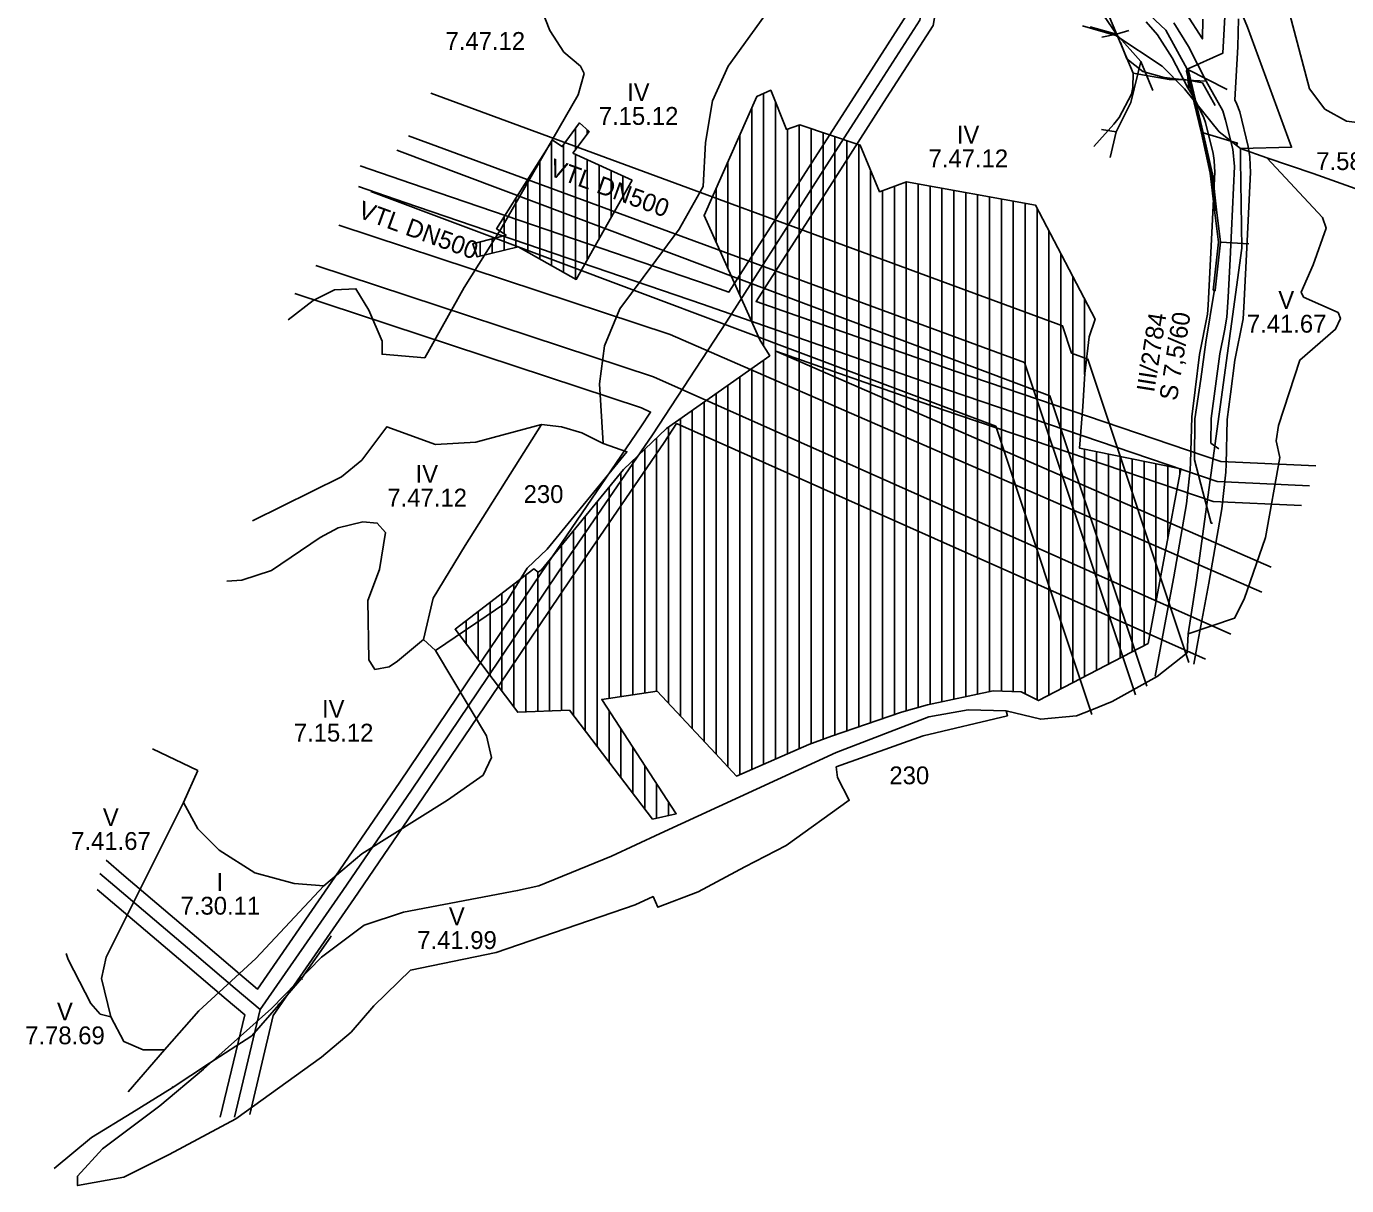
# Model space of a CAD drawing. Extents: x -694504 to -690518, y -983661 to -978958.
# Drawn here: x -694504 to -693394, y -982493 to -981518 of the extents above; entities that cross this region are included whole.
import ezdxf

# ---------------------------------------------------------------- set-up
doc = ezdxf.new("R2010")
doc.units = 0
for name, color, linetype in [('bezpečnostní pásmo', 7, 'Continuous'), ('BPEJ', 7, 'Continuous'), ('kabelové a venkovní rozvody telefonu', 7, 'Continuous'), ('ochranné pásmo silnic', 7, 'Continuous'), ('ochranné pásmo vedení', 7, 'Continuous'), ('odvodněné pozemky', 7, 'Continuous'), ('třídy přednosti v ochraně ZP', 7, 'Continuous'), ('vedení NN', 7, 'Continuous'), ('vedení VN 35kV', 7, 'Continuous'), ('vedení VVN 110kV', 7, 'Continuous'), ('vedení VVN 220kV', 7, 'Continuous'), ('vedení VVN 400kV', 7, 'Continuous'), ('vodovodní řad', 7, 'Continuous'), ('VTL plynovod', 7, 'Continuous')]:
    doc.layers.add(name, color=color, linetype=linetype)

msp = doc.modelspace()

# ---------------------------------------------------------------- linework, layer by layer
at = {"layer": 'bezpečnostní pásmo'}
for points in [[(-693526.8, -982053), (-693611.7, -981798.1), (-693625.5, -981792.9), (-693633.2, -981769.9), (-694164.4, -981574.4)], [(-694214.8, -981657), (-693689.3, -981854.4), (-693608.5, -982096.8)]]:
    msp.add_lwpolyline(points, dxfattribs=at)
at = {"layer": 'BPEJ'}
for p, q in [((-694263.4, -981748.8), (-694284.2, -981764.8)), ((-694323.4, -981983.8), (-694335.8, -981984.6)), ((-694360.4, -982143.8), (-694398.3, -982125.5)), ((-694372.4, -982170.8), (-694360.4, -982143.8)), ((-694469.4, -982302.8), (-694471.1, -982297.6)), ((-694450.4, -982339.8), (-694469.4, -982302.8)), ((-694442.4, -982348.8), (-694450.4, -982339.8)), ((-694433.4, -982350.8), (-694442.4, -982348.8)), ((-694419, -982413.9), (-694388.4, -982378.8))]:
    msp.add_line(p, q, dxfattribs=at)
for points in [[(-694038.4, -981384.8), (-694071.4, -981426.8), (-694078.4, -981449.8), (-694078.4, -981485.8), (-694064.4, -981521.8), (-694052.4, -981539.8), (-694038.4, -981551.8), (-694035.4, -981557.8), (-694040.4, -981575.8), (-694105.4, -981688.8), (-694136.4, -981737.8), (-694169.4, -981796.8), (-694205.4, -981793.8), (-694205.4, -981782.8), (-694216.4, -981756.8), (-694227.4, -981738.8), (-694245.4, -981739.8), (-694263.4, -981748.8)], [(-693904.4, -981450.8), (-693893.4, -981452.8), (-693883.4, -981459.8), (-693874.4, -981467.8), (-693870.4, -981480.8), (-693873.4, -981494.8), (-693914.4, -981551.8), (-693927.4, -981580.8), (-693933.4, -981615.8), (-693935.4, -981652.8), (-693955.4, -981688.8), (-694005.4, -981755.8), (-694018.4, -981786.8), (-694022.4, -981818.8), (-694019.4, -981868.8)], [(-693237.4, -981494.8), (-693223.4, -981526.8), (-693218.4, -981584.8), (-693210.4, -981605.8), (-693195.4, -981621.8), (-693120.4, -981666.8), (-693101.4, -981671.8), (-693080.4, -981680.8), (-693041.4, -981711.8), (-693078.4, -981753.8), (-693108.4, -981714.8), (-693141.4, -981687.8), (-693185.4, -981672.8), (-693254.4, -981657.8), (-693276.4, -981647.8), (-693345.4, -981606.8), (-693363.4, -981601.8), (-693394.4, -981597.8), (-693412.4, -981587.8), (-693425.4, -981570.8), (-693452.4, -981468.8)], [(-693492.4, -981482.8), (-693477.4, -981518.8), (-693440.4, -981619.8), (-693483.4, -981620.8), (-693501.4, -981606.8), (-693530.4, -981570.8), (-693549.4, -981551.8), (-693588.4, -981525.8), (-693616.4, -981517.8)], [(-693461.4, -981628.8), (-693422.4, -981641.8), (-693352.4, -981666.8)], [(-694071.4, -981852.8), (-694126.4, -981867.8), (-694160.4, -981869.8), (-694201.4, -981854.8), (-694222.4, -981882.8), (-694239.4, -981896.8), (-694314.4, -981933.8)], [(-694170.4, -982033.8), (-694192.4, -982051.8), (-694199.4, -982056.8), (-694211.4, -982058.8), (-694216.4, -982050.8), (-694217.4, -982000.8), (-694207.4, -981974.8), (-694202.4, -981943.8), (-694209.4, -981935.8), (-694221.4, -981934.8), (-694242.4, -981939.8), (-694257.4, -981947.8), (-694298.4, -981975.8), (-694323.4, -981983.8)], [(-693680.4, -982093.8), (-693651.4, -982100.8), (-693621.4, -982097.8), (-693608.4, -982092.8), (-693591.4, -982085.8), (-693553.4, -982064.8), (-693528.4, -982044.8), (-693527.4, -982028.8)], [(-694254.4, -982240.8), (-694222.4, -982213.8), (-694150.4, -982168.8), (-694120.4, -982147.8), (-694113.4, -982132.8), (-694117.4, -982114.8), (-694160.4, -982042.8)]]:
    msp.add_lwpolyline(points, dxfattribs=at)
for points in [[(-693461.4, -981628.8), (-693414.4, -981678.8), (-693411.4, -981687.8), (-693422.4, -981718.8), (-693432.4, -981741.8), (-693430.4, -981745.8), (-693401.4, -981758.8), (-693399.4, -981763.8), (-693403.4, -981772.8), (-693433.4, -981798.8), (-693451.4, -981853.8), (-693453.4, -981866.8), (-693450.4, -981880.8), (-693462.4, -981947.8), (-693480.4, -981999.8), (-693488.4, -982015.8), (-693527.4, -982028.8), (-693520.4, -981983.8), (-693482.4, -981704.8), (-693483.4, -981630.8), (-693483.4, -981620.8), (-693461.4, -981628.8)], [(-694019.4, -981868.8), (-693999.4, -981875.8), (-694066.4, -981957.8), (-694083.4, -981973.8), (-694101.4, -982002.8), (-694160.4, -982042.8), (-694170.4, -982033.8), (-694162.4, -981998.8), (-694135.4, -981954.8), (-694071.4, -981852.8), (-694054.4, -981854.8), (-694037.4, -981859.8), (-694019.4, -981868.8)], [(-693680.4, -982093.8), (-693679.4, -982097.8), (-693750.4, -982114.8), (-693823.4, -982140.8), (-693822.4, -982149.8), (-693812.4, -982168.8), (-693865.4, -982206.8), (-693900.4, -982224.8), (-693939.4, -982245.8), (-693973.4, -982258.8), (-693977.4, -982249.8), (-693992.4, -982256.8), (-694109.4, -982296.8), (-694181.4, -982311.8), (-694212.4, -982341.8), (-694231.4, -982363.8), (-694256.4, -982384.8), (-694328.4, -982436.8), (-694384.4, -982466.8), (-694422.4, -982485.8), (-694461.4, -982492.8), (-694461.4, -982484.8), (-694440.4, -982461.8), (-694392.4, -982425.8), (-694355.4, -982394.8), (-694298.4, -982343.8), (-694256.4, -982300.8), (-694220.4, -982273.8), (-694187.4, -982262.8), (-694091.4, -982244.8), (-694073.4, -982240.8), (-694012.4, -982215.8), (-693971.4, -982196.8), (-693823.4, -982128.8), (-693745.4, -982098.8), (-693712.4, -982092.8), (-693680.4, -982093.8)], [(-694254.4, -982240.8), (-694311.4, -982301.8), (-694359.4, -982345.8), (-694388.4, -982378.8), (-694406.4, -982378.8), (-694422.4, -982371.8), (-694433.4, -982350.8), (-694441.4, -982318.8), (-694437.4, -982300.8), (-694372.4, -982170.8), (-694360.4, -982192.8), (-694342.4, -982210.8), (-694312.4, -982229.8), (-694279.4, -982238.8), (-694254.4, -982240.8)]]:
    msp.add_lwpolyline(points, close=True, dxfattribs=at)
at = {"layer": 'kabelové a venkovní rozvody telefonu'}
for points in [[(-693501.7, -981873.5), (-693508.5, -981868.6), (-693508, -981847.9), (-693500.7, -981793.5), (-693496.8, -981774.2), (-693494.8, -981762.6), (-693493.8, -981745.9), (-693492, -981714), (-693491, -981689.9), (-693488.4, -981636.1), (-693489.9, -981621.4), (-693496, -981597.1), (-693498.4, -981589.2), (-693512.3, -981564.3), (-693527.1, -981535.2), (-693539.4, -981515.1)], [(-693512.3, -981564.3), (-693528.4, -981563.5), (-693547.7, -981561.1), (-693565.6, -981556.1), (-693579.1, -981545.6), (-693584.3, -981531.8)]]:
    msp.add_lwpolyline(points, dxfattribs=at)
at = {"layer": 'ochranné pásmo silnic'}
for points in [[(-693562.8, -981514.3), (-693553.1, -981525.4), (-693541, -981544.6), (-693527.6, -981569.9), (-693520.8, -981581.7), (-693514.3, -981595.2), (-693512.9, -981599), (-693506.4, -981625), (-693505.6, -981630.9), (-693505.2, -981636.4), (-693505.1, -981640.6), (-693507.7, -981697.3), (-693510.6, -981752.6), (-693511.1, -981760.2), (-693517.8, -981794), (-693521.6, -981823.8), (-693524.4, -981846.6), (-693525.5, -981885.2), (-693525.7, -981890.9), (-693528.8, -981919.7), (-693539.5, -981981), (-693548.8, -982030.1), (-693555.3, -982064.6)], [(-693515, -981512.2), (-693515.5, -981528.8), (-693529, -981507.4)], [(-693522.7, -982054.3), (-693519.3, -982035.6), (-693510, -981986.3), (-693499.1, -981923.9), (-693495.8, -981893.1), (-693495.5, -981886.2), (-693494.5, -981848.8), (-693491.9, -981827.5), (-693488.2, -981798.8), (-693481.3, -981764), (-693480.7, -981754.3), (-693477.7, -981698.8), (-693475.1, -981640.9), (-693475.3, -981635.1), (-693475.7, -981627.9), (-693476.9, -981619.3), (-693484.1, -981590.2), (-693486.6, -981583.5), (-693488.3, -981579.9), (-693485.7, -981535.3), (-693485, -981512)]]:
    msp.add_lwpolyline(points, dxfattribs=at)
at = {"layer": 'ochranné pásmo vedení'}
for points in [[(-693651.4, -980679.7), (-693656.9, -980718.3), (-693667.6, -980824.3), (-693683.9, -980933.2), (-693690.1, -980989.4), (-693696.4, -981035.2), (-693702.4, -981085.5), (-693708.3, -981136.8), (-693719.8, -981230.7), (-693726.1, -981276.8), (-693732, -981321.5), (-693748.8, -981419.3), (-693764.3, -981508.7), (-693803.4, -981569.5), (-693844.2, -981633.2), (-693885.7, -981697.9), (-693913.6, -981741.6), (-693930.3, -981735.7), (-694180.6, -981650.3), (-694223.8, -981635.4)], [(-693420.2, -981887.7), (-693499.9, -981883.9), (-693723.4, -981808), (-693890.8, -981749.5), (-693865.9, -981710.6), (-693824.4, -981645.9), (-693783.6, -981582.2), (-693742, -981517.4), (-693725.6, -981423.3), (-693708.8, -981325), (-693702.8, -981280), (-693696.5, -981233.7), (-693685, -981139.6), (-693679, -981088.3), (-693674.5, -981050.1), (-693632.1, -981056.5), (-693561, -981067.7), (-693486.4, -981082.6), (-693375.3, -981103.5), (-693388.6, -981133.8), (-693412.6, -981189), (-693432.6, -981241.5), (-693452.6, -981307.6)], [(-694278.7, -981742.9), (-693987.2, -981839), (-693979.5, -981842.5), (-693987.7, -981855), (-694066.6, -981970.3), (-694126.4, -982059), (-694190.4, -982153.7), (-694248.1, -982238.1), (-694310.1, -982327.6), (-694321.4, -982318.1), (-694355.7, -982288.8), (-694422.4, -982232.1), (-694437.4, -982219.3)], [(-693457.6, -981972.8), (-693712.1, -981862), (-693874.3, -981791.3), (-693734.4, -981840.2), (-693506.3, -981917.6), (-693432.1, -981921.1)], [(-694316.7, -982432.9), (-694296.9, -982349.7), (-694228.7, -982251.4), (-694171, -982166.9), (-694106.9, -982072.1), (-694047.2, -981983.5), (-693968.2, -981868.1), (-693957.7, -981852.1), (-693740.7, -981948.8), (-693512.9, -982050.3)], [(-694444.9, -982243.8), (-694437.6, -982249.9), (-694371, -982306.7), (-694336.6, -982336), (-694320.9, -982349.2), (-694341.4, -982435.2)]]:
    msp.add_lwpolyline(points, dxfattribs=at)
at = {"layer": 'odvodněné pozemky'}
for p, q in [((-693884.5, -981787.1), (-693884.5, -981574.7)), ((-693874.5, -982134.3), (-693874.5, -981582)), ((-693894.5, -981766.8), (-693894.5, -981586.9)), ((-694042.8, -981622.1), (-694042.8, -981604.1)), ((-693854.5, -982125.6), (-693854.5, -981601.1)), ((-693844.5, -982121.4), (-693844.5, -981604.2)), ((-694062.8, -981719.4), (-694062.8, -981615.1)), ((-694032.8, -981608.8), (-694032.8, -981605.2)), ((-693904.5, -981744.5), (-693904.5, -981609.4)), ((-693864.5, -982129.9), (-693864.5, -981604.6)), ((-693834.5, -982117.6), (-693834.5, -981607.6)), ((-693824.5, -982113.9), (-693824.5, -981611)), ((-693814.5, -982110.5), (-693814.5, -981614.4)), ((-694052.8, -981725), (-694052.8, -981617.9)), ((-694042.8, -981730.5), (-694042.8, -981625.7)), ((-693804.5, -982107.1), (-693804.5, -981617.8)), ((-694072.8, -981713.8), (-694072.8, -981630.9)), ((-694032.8, -981714.5), (-694032.8, -981630.2)), ((-694022.8, -981696.8), (-694022.8, -981634.8)), ((-693914.5, -981722.1), (-693914.5, -981631.8)), ((-694082.8, -981708.3), (-694082.8, -981646.7)), ((-694012.8, -981679.1), (-694012.8, -981639.3)), ((-694002.8, -981661.4), (-694002.8, -981643.9)), ((-693794.5, -982103.7), (-693794.5, -981639.1)), ((-693924.5, -981699.7), (-693924.5, -981654.3)), ((-693784.5, -982100.3), (-693784.5, -981656.3)), ((-693774.5, -982097), (-693774.5, -981652.7)), ((-693764.5, -982093.8), (-693764.5, -981649.1)), ((-693754.5, -982090.8), (-693754.5, -981650.8)), ((-693744.5, -982088.1), (-693744.5, -981652.6)), ((-693734.5, -982086), (-693734.5, -981654.4)), ((-693724.5, -982083.8), (-693724.5, -981656.2)), ((-693714.5, -982081.7), (-693714.5, -981658)), ((-693704.5, -982079.6), (-693704.5, -981659.8)), ((-694092.8, -981704.1), (-694092.8, -981662.5)), ((-693694.5, -982077.4), (-693694.5, -981661.6)), ((-693684.5, -982077.1), (-693684.5, -981663.4)), ((-693674.5, -982077.4), (-693674.5, -981665.2)), ((-693664.5, -982079.4), (-693664.5, -981667)), ((-694102.8, -981692.5), (-694102.8, -981678.2)), ((-693934.5, -981677.3), (-693934.5, -981676.8)), ((-693654.5, -982084.4), (-693654.5, -981671.1)), ((-693644.5, -982080.3), (-693644.5, -981690.2)), ((-694122.8, -981711.2), (-694122.8, -981699.4)), ((-694112.8, -981708.9), (-694112.8, -981696.8)), ((-694102.8, -981706.5), (-694102.8, -981694.2)), ((-693634.5, -982075.1), (-693634.5, -981709.4)), ((-693624.5, -982069.9), (-693624.5, -981728.5)), ((-693614.5, -981810.8), (-693614.5, -981747.6)), ((-693884.5, -982138.6), (-693884.5, -981798.8)), ((-693904.5, -982147.3), (-693904.5, -981812.9)), ((-693894.5, -982142.9), (-693894.5, -981805.8)), ((-693914.5, -982140.8), (-693914.5, -981819.9)), ((-693934.5, -982119.5), (-693934.5, -981834)), ((-693924.5, -982130.2), (-693924.5, -981827)), ((-693954.5, -982098.1), (-693954.5, -981848.2)), ((-693944.5, -982108.8), (-693944.5, -981841.1)), ((-693964.5, -982087.3), (-693964.5, -981855.2)), ((-693974.5, -982077.1), (-693974.5, -981864.3)), ((-693984.5, -982078.6), (-693984.5, -981873.8)), ((-693614.5, -982064.7), (-693614.5, -981873.6)), ((-693604.5, -982059.5), (-693604.5, -981875.7)), ((-693594.5, -982054.3), (-693594.5, -981877.7)), ((-693584.5, -982049.2), (-693584.5, -981879.8)), ((-693574.5, -982044), (-693574.5, -981881.8)), ((-693994.5, -982080.1), (-693994.5, -981883.3)), ((-693564.5, -982038.8), (-693564.5, -981883.8)), ((-693554.5, -982001.2), (-693554.5, -981885.9)), ((-693544.5, -981948.1), (-693544.5, -981887.9)), ((-693534.5, -981895.1), (-693534.5, -981890)), ((-694004.5, -982081.6), (-694004.5, -981893.4)), ((-694014.5, -982083.1), (-694014.5, -981905.6)), ((-694024.5, -982123.7), (-694024.5, -981917.9)), ((-694034.5, -982110.6), (-694034.5, -981930.1)), ((-694044.5, -982097.4), (-694044.5, -981942.3)), ((-694054.5, -982093.4), (-694054.5, -981954.6)), ((-694064.5, -982093.8), (-694064.5, -981966.8)), ((-694084.5, -982094.7), (-694084.5, -981979.5)), ((-694074.5, -982094.2), (-694074.5, -981976.7)), ((-694094.5, -982090.7), (-694094.5, -981987.2)), ((-694114.5, -982064.1), (-694114.5, -982002.5)), ((-694104.5, -982077.4), (-694104.5, -981994.9)), ((-694124.5, -982050.8), (-694124.5, -982010.2)), ((-694134.5, -982037.6), (-694134.5, -982017.9)), ((-694014.5, -982136.8), (-694014.5, -982093.4)), ((-694004.5, -982149.9), (-694004.5, -982108.8)), ((-693994.5, -982163), (-693994.5, -982124.1)), ((-693984.5, -982176.2), (-693984.5, -982139.5)), ((-693974.5, -982184), (-693974.5, -982154.9)), ((-693964.5, -982181.7), (-693964.5, -982170.3))]:
    msp.add_line(p, q, dxfattribs=at)
for points in [[(-693561.2, -982037.1), (-693533.5, -981890.2), (-693618.9, -981872.7), (-693616, -981837.9), (-693614.4, -981810.1), (-693610.6, -981779.1), (-693605.7, -981764.5), (-693655.8, -981668.6), (-693764.2, -981649), (-693786.9, -981657.2), (-693803.2, -981618.2), (-693854, -981601), (-693865.3, -981604.9), (-693878.5, -981571.9), (-693890.2, -981577.3), (-693934.6, -981677.1), (-693887.5, -981782.4), (-693879.3, -981795.1), (-693966.1, -981856.4), (-694002.4, -981890.9), (-694071.3, -981975.2), (-694074, -981977), (-694077.7, -981974.3), (-694143.9, -982025.1), (-694091.3, -982094.9), (-694047.8, -982093.1), (-693977.9, -982184.7), (-693958, -982180.2), (-694020.6, -982084), (-693974.1, -982077), (-693925, -982129.6), (-693907.2, -982148.5), (-693846.5, -982122.1), (-693827.4, -982114.9)], [(-693994.9, -981647.5), (-694042, -981730.9), (-694091, -981703.7), (-694125.4, -981711.9), (-694129.1, -981701), (-694101, -981693.7), (-694109.1, -981688.3), (-694062, -981613.9), (-694053.8, -981619.3), (-694039.3, -981599.4), (-694031.2, -981606.6), (-694044.8, -981624.8)], [(-694044.8, -981624.8), (-693994.9, -981647.5)], [(-693827.4, -982114.9), (-693768.5, -982094.9), (-693746.7, -982088.6), (-693691.4, -982076.8), (-693667.9, -982077.7), (-693653.4, -982085), (-693561.2, -982037.1)]]:
    msp.add_lwpolyline(points, dxfattribs=at)
at = {"layer": 'vedení NN'}
for points in [[(-693609.5, -981492.6), (-693587.7, -981524.9)], [(-693582.3, -981487.2), (-693546.2, -981521.4), (-693528.3, -981554.3)], [(-693528.3, -981554.3), (-693498.2, -981540.6), (-693495.9, -981499.8)], [(-693587.7, -981524.9), (-693609.9, -981518.5)], [(-693587.7, -981524.9), (-693600, -981527.2)], [(-693587.7, -981524.9), (-693577.3, -981521.6)], [(-693587.7, -981524.9), (-693567.3, -981547.7)], [(-693567.3, -981547.7), (-693575.7, -981582.3), (-693588, -981607)], [(-693567.3, -981547.7), (-693557.1, -981572.2)], [(-693504.2, -981740.1), (-693506.3, -981739.9), (-693501.8, -981699.6), (-693505.2, -981672.7), (-693508.8, -981641.7), (-693516.3, -981608.1), (-693528.7, -981556), (-693528.3, -981554.3)], [(-693528.3, -981554.3), (-693526.8, -981570.8)], [(-693528.3, -981554.3), (-693494.6, -981571.3)], [(-693528.3, -981554.3), (-693527.2, -981555.2), (-693514.7, -981607.7)], [(-693528.3, -981554.3), (-693515.5, -981607.9), (-693508, -981641.5), (-693508.2, -981641.6), (-693508, -981642.8), (-693507.8, -981642.8)], [(-693588, -981607), (-693600.4, -981604.9)], [(-693588, -981607), (-693593.1, -981628.5)], [(-693514.7, -981607.7), (-693486, -981616.4), (-693486.7, -981617.7)], [(-693514.7, -981607.7), (-693507.2, -981641.4), (-693507.1, -981642), (-693503.7, -981672.5), (-693500.1, -981699.6)], [(-693504.6, -981671.4), (-693504.8, -981671.4), (-693504.7, -981672.6), (-693504.5, -981672.6), (-693507.8, -981642.8)], [(-693500.1, -981699.6), (-693504.7, -981740), (-693505.7, -981741.2), (-693512.5, -981783.7), (-693516.8, -981814.9), (-693521.7, -981848.2), (-693522, -981882.7), (-693515, -981909.5), (-693508.2, -981935.8), (-693507.1, -981936)], [(-693500.1, -981699.6), (-693500.1, -981699.8), (-693499.7, -981699.8), (-693499.7, -981699.6)], [(-693499.7, -981699.6), (-693499.7, -981699.4), (-693499.9, -981699.4), (-693499.9, -981699.6), (-693476.3, -981700.9)], [(-694273.1, -982318.6), (-694248.8, -982283.9), (-694248.1, -982282.8)], [(-694292.2, -982340.8), (-694273.1, -982318.6)], [(-694273.1, -982318.6), (-694274.1, -982317.7)], [(-694273.1, -982318.6), (-694272.2, -982319.5)], [(-694382, -982410.5), (-694350.6, -982389.9), (-694314.9, -982366.9), (-694292.2, -982340.8)], [(-694292.2, -982340.8), (-694293.1, -982339.9)], [(-694481, -982478.5), (-694449.6, -982452.5), (-694415.9, -982431.6), (-694382, -982410.5)], [(-694381.2, -982409.5), (-694382, -982410.5)]]:
    msp.add_lwpolyline(points, dxfattribs=at)
at = {"layer": 'vedení VN 35kV'}
for points in [[(-694329.4, -982435.4), (-694307.8, -982344.9), (-694238.4, -982244.8), (-694180.7, -982160.3), (-694116.7, -982065.5), (-694056.9, -981976.9), (-693978, -981861.5), (-693915.8, -981766.7), (-693875.8, -981704.3), (-693834.3, -981639.5), (-693793.5, -981575.8), (-693753.2, -981513.1), (-693737.2, -981421.3), (-693720.4, -981323.2), (-693714.4, -981278.4), (-693708.1, -981232.2), (-693696.7, -981138.2), (-693690.7, -981086.9), (-693684.7, -981036.7), (-693678.5, -980990.9), (-693672.3, -980934.7), (-693656, -980825.7), (-693645.3, -980719.7), (-693639.5, -980679.3)], [(-694442.6, -982230.3), (-694430, -982241), (-694363.4, -982297.8), (-694329, -982327), (-694307.8, -982344.9)]]:
    msp.add_lwpolyline(points, dxfattribs=at)
at = {"layer": 'vedení VVN 110kV'}
msp.add_lwpolyline([(-694225.1, -981652.9), (-694186.1, -981666.4), (-693935.9, -981751.8), (-693728.9, -981824.1), (-693503.1, -981900.8), (-693425.5, -981904.4)], dxfattribs=at)
at = {"layer": 'vedení VVN 220kV'}
msp.add_lwpolyline([(-694241.7, -981685.4), (-693963.2, -981777.2), (-693721.1, -981882.6), (-693465.5, -981993.9)], dxfattribs=at)
at = {"layer": 'vedení VVN 400kV'}
msp.add_lwpolyline([(-694261.1, -981719.3), (-693977.1, -981812.9), (-693729.3, -981923.2), (-693491.6, -982029.1)], dxfattribs=at)
at = {"layer": 'vodovodní řad'}
for points in [[(-693635.1, -981331.5), (-693640.5, -981332.4), (-693667.2, -981346.4), (-693662.2, -981353.6), (-693634.6, -981410), (-693649.2, -981453.3), (-693640, -981474.4), (-693621.5, -981467), (-693613.8, -981489.8), (-693602.1, -981490.2), (-693573.8, -981557.6), (-693543.3, -981563), (-693530.4, -981563), (-693515.5, -981565.7), (-693504.6, -981584.7)], [(-693573.8, -981557.6), (-693574.1, -981569.7), (-693575, -981575.1), (-693585.4, -981594.9), (-693589.9, -981600.3), (-693606.7, -981619.3)]]:
    msp.add_lwpolyline(points, dxfattribs=at)
at = {"layer": 'VTL plynovod'}
for points in [[(-694183.1, -981610.2), (-693665, -981800.8), (-693571.8, -982080.3)], [(-694192.9, -981622.4), (-693643.7, -981828.8), (-693562.3, -982073)]]:
    msp.add_lwpolyline(points, dxfattribs=at)

# ---------------------------------------------------------------- texts
at = {"layer": 'ochranné pásmo silnic'}
for s, p in [('S 7,5/60', (-693537, -981833.5)), ('III/2784', (-693556.1, -981826.4))]:
    msp.add_text(s, height=15, rotation=81, dxfattribs=at).set_placement(p)
at = {"layer": 'třídy přednosti v ochraně ZP'}
for s, p in [('7.47.12', (-694152, -981538)), ('IV', (-693999.3, -981581)), ('7.15.12', (-694023.1, -981601)), ('IV', (-693722, -981616.7)), ('7.47.12', (-693745.8, -981636.7)), ('7.58.00', (-693419.7, -981639)), ('V', (-693451.6, -981755.7)), ('7.41.67', (-693478.1, -981775.7)), ('IV', (-694177.2, -981901.9)), ('230', (-694086.3, -981918.9)), ('7.47.12', (-694200.9, -981921.9)), ('IV', (-694255.9, -982099.5)), ('7.15.12', (-694279.6, -982119.5)), ('230', (-693778.7, -982155.4)), ('V', (-694440.2, -982190.6)), ('7.41.67', (-694466.8, -982210.6)), ('I', (-694344.5, -982245)), ('7.30.11', (-694374.8, -982265)), ('V', (-694149.2, -982273.9)), ('7.41.99', (-694175.8, -982293.9)), ('V', (-694478.8, -982354)), ('7.78.69', (-694505.5, -982374))]:
    msp.add_text(s, height=15, dxfattribs=at).set_placement(p)
at = {"layer": 'VTL plynovod'}
for p in [(-694065.9, -981643.2), (-694226.6, -981678.6)]:
    msp.add_text('VTL DN500', height=15, rotation=340, dxfattribs=at).set_placement(p)

doc.saveas('drawing.dxf')
